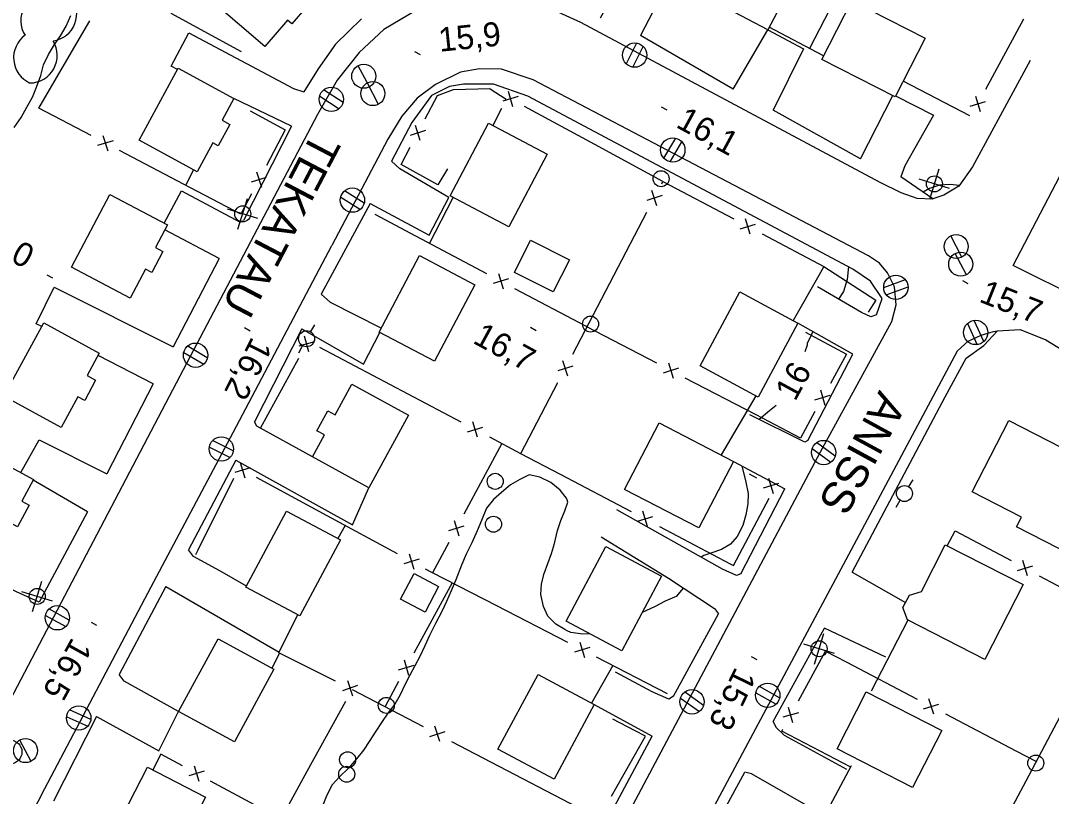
# Model space of a CAD drawing. Extents: x 219136 to 222520, y 5421589 to 5424530.
# Drawn here: x 220439.8 to 220568.6, y 5423964.5 to 5424061.3 of the extents above; entities that cross this region are included whole.
import ezdxf

# ---------------------------------------------------------------- set-up
doc = ezdxf.new("R2010")
doc.units = 0
for name, color, linetype in [('Level 19', 7, 'Continuous'), ('Level 2', 7, 'Continuous'), ('Level 21', 7, 'Continuous'), ('Level 3', 7, 'Continuous'), ('Level 31', 7, 'Continuous'), ('Level 36', 7, 'Continuous'), ('Level 37', 7, 'Continuous'), ('Level 44', 7, 'Continuous')]:
    doc.layers.add(name, color=color, linetype=linetype)

msp = doc.modelspace()

# ---------------------------------------------------------------- linework, layer by layer
at = {"layer": 'Level 19'}
for points in [[(220512.29, 5424061.68), (220516.28, 5424068.95), (220520.94, 5424066.53), (220517.29, 5424059.47)], [(220459.45, 5424055.23), (220458.64, 5424055.64), (220460.88, 5424059.78), (220473.94, 5424052.85), (220475.23, 5424052.42)], [(220528.84, 5424052.74), (220533.2, 5424060.17), (220537.65, 5424057.78), (220533.86, 5424050.12)], [(220473.67, 5424048.15), (220466.49, 5424051.61)], [(220544.75, 5424044.06), (220548.79, 5424051.95)], [(220549.15, 5424051.91), (220553.87, 5424049.5), (220550.32, 5424043.18), (220549.81, 5424041.8)], [(220483.53, 5424038.48), (220490.9, 5424034.54), (220493.33, 5424039.23), (220487.21, 5424042.8), (220486.18, 5424043.78)], [(220457.77, 5424036.03), (220459.94, 5424040.05), (220467.29, 5424036.17), (220467.68, 5424036.36)], [(220464.64, 5424031.6), (220457.88, 5424035.19)], [(220442.48, 5424023.11), (220441.81, 5424023.46), (220444.03, 5424028.03), (220458.89, 5424020.58)], [(220546.77, 5424024.57), (220546.06, 5424024.34), (220544.88, 5424024.86), (220539.38, 5424028.07)], [(220484.9, 5424022.92), (220478.57, 5424026.1), (220477.39, 5424027.16)], [(220543.79, 5424019.65), (220536.94, 5424023.56)], [(220474.97, 5424022.84), (220482.66, 5424018.43), (220484.72, 5424022.39)], [(220456.39, 5424015.96), (220449.52, 5424019.49)], [(220538.19, 5424008.9), (220537.8, 5424008.69), (220530.93, 5424012.1)], [(220476.29, 5424006.83), (220469.36, 5424010.66), (220469.06, 5424011.21)], [(220439.88, 5424004.89), (220442.15, 5424008.97), (220450.6, 5424004.71)], [(220466.72, 5424006.45), (220481.3, 5423998.36), (220483.34, 5424002.98)], [(220528.88, 5424006.28), (220535.31, 5424002.87)], [(220448.19, 5424000), (220441.41, 5424003.93)], [(220529.8, 5423992.23), (220529.28, 5423992.02), (220527.54, 5423992.82), (220514.32, 5424000.25)], [(220512.36, 5423996.85), (220520.77, 5423991.69), (220526.51, 5423987.91), (220527.03, 5423987.26)], [(220442.18, 5423988.72), (220439.33, 5423990.01), (220428.37, 5423995.69)], [(220468.06, 5423990.72), (220464.74, 5423992.63), (220461.43, 5423994.41), (220460.8, 5423995.24)], [(220543.71, 5423992.44), (220550.38, 5423988.65)], [(220458, 5423990.64), (220472.15, 5423982.47)], [(220547.91, 5423981.83), (220540.27, 5423985.44)], [(220449.34, 5423974.44), (220457.1, 5423970.16), (220459.59, 5423975.04), (220452.78, 5423978.86), (220452.15, 5423979.68)], [(220521.42, 5423976.98), (220520.81, 5423976.61), (220518.73, 5423977.5), (220514.16, 5423979.96)], [(220511.49, 5423975.93), (220518.72, 5423971.97)], [(220533.85, 5423973.82), (220534.2, 5423973.09), (220535.25, 5423972.08), (220543, 5423967.84)], [(220540.03, 5423962.18), (220531.14, 5423967.27), (220530.32, 5423967.46)]]:
    msp.add_lwpolyline(points, dxfattribs=at)
at = {"layer": 'Level 2'}
for points in [[(220439.05, 5424047.96), (220439.91, 5424049.2), (220440.64, 5424050.5), (220441.32, 5424051.74), (220441.84, 5424053.01), (220442.37, 5424054.45), (220442.69, 5424055.8), (220443.35, 5424057.09), (220444.06, 5424058.32), (220444.82, 5424059.41), (220445.53, 5424060.61), (220446.14, 5424061.94)], [(220557.1, 5424040.73), (220555.95, 5424040.85), (220554.64, 5424040.79), (220553.37, 5424040.34), (220552.6, 5424039.9)], [(220543.26, 5424030.6), (220543.08, 5424029), (220542.63, 5424027.51), (220542.03, 5424026.52)], [(220538.82, 5424022.49), (220538.46, 5424021.75), (220538.1, 5424021.05), (220538.09, 5424020.78), (220537.81, 5424019.95)], [(220534.23, 5424013.26), (220533.38, 5424012.6), (220532.12, 5424011.51)], [(220529.95, 5424005.71), (220530.46, 5424003.68), (220530.72, 5424002.26), (220530.7, 5424001), (220530.43, 5423999.6), (220530.07, 5423998.29), (220529.36, 5423996.92), (220528.52, 5423995.94), (220527.42, 5423995.3), (220526.07, 5423994.82), (220525.2, 5423994.55), (220524.87, 5423994.32)], [(220507.34, 5423998.91), (220507.84, 5424000.1), (220508.19, 5424001.17), (220508.14, 5424001.47), (220508.02, 5424001.69), (220507.23, 5424002.67), (220506.07, 5424003.63), (220504.72, 5424004.31), (220503.37, 5424004.6), (220502.23, 5424004.01), (220501.05, 5424003.35), (220499.91, 5424002.4), (220498.93, 5424001.53), (220498.05, 5424000.42), (220497.41, 5423998.91), (220496.86, 5423997.59), (220496.21, 5423996.1), (220495.49, 5423994.68), (220494.91, 5423993.33), (220494.22, 5423991.5), (220493.64, 5423990.11), (220493.04, 5423988.78), (220492.47, 5423987.55), (220491.69, 5423986.02), (220490.94, 5423984.53), (220490.34, 5423983.24), (220489.73, 5423981.91), (220489.11, 5423980.74), (220488.46, 5423979.58), (220487.85, 5423978.4), (220487.27, 5423977.15), (220486.58, 5423975.98), (220485.72, 5423974.83), (220484.92, 5423973.67), (220484.24, 5423972.6), (220483.4, 5423971.3), (220482.68, 5423970.24), (220481.82, 5423969.13), (220480.8, 5423967.97), (220479.68, 5423966.9), (220478.78, 5423965.91), (220478.09, 5423964.59), (220477.51, 5423963.16)], [(220510.96, 5423984.76), (220510.07, 5423984.7), (220508.57, 5423984.9), (220508.11, 5423985.14), (220507.84, 5423985.28), (220506.69, 5423985.95), (220505.7, 5423986.96), (220505.16, 5423988.16), (220504.83, 5423989.66), (220504.9, 5423991), (220505.26, 5423992.28), (220505.72, 5423993.55), (220506.17, 5423994.79), (220506.52, 5423996.01), (220506.92, 5423997.67), (220507.34, 5423998.91)], [(220522.62, 5423990.47), (220521.75, 5423989.42), (220521.51, 5423989.31), (220520.35, 5423988.81), (220519.03, 5423988.12), (220517.49, 5423987.42)]]:
    msp.add_lwpolyline(points, dxfattribs=at)
at = {"layer": 'Level 21'}
for points in [[(220553.81, 5424039.07), (220553.73, 5424039.04), (220551.84, 5424039.1), (220549.83, 5424039.83), (220547.23, 5424041.1), (220509.83, 5424061.1), (220505.16, 5424063.19), (220501.63, 5424064.07), (220497.84, 5424064.31), (220493.34, 5424063.78), (220489.3, 5424062.62), (220485.23, 5424060.19), (220482.14, 5424057.35), (220479.4, 5424053.9), (220476.93, 5424049.58), (220459.72, 5424016.93), (220442.62, 5423984.31), (220432.48, 5423964.99)], [(220482.45, 5424061.53), (220479.2, 5424058.39), (220477, 5424055.31), (220475.23, 5424052.42)], [(220528.84, 5424052.74), (220517.29, 5424059.47)], [(220565.98, 5424056.33), (220558.77, 5424043.06), (220557.04, 5424040.64), (220555.17, 5424039.54), (220553.81, 5424039.07)], [(220482, 5423898.19), (220509.57, 5423950.66), (220539.78, 5424007.46), (220548.68, 5424023.76), (220549.21, 5424025.83), (220549.01, 5424028.08), (220548.12, 5424029.81), (220547.12, 5424031.04), (220545.76, 5424031.95), (220503.88, 5424053.94), (220499.93, 5424055.25), (220497.16, 5424055.31), (220494.79, 5424054.89), (220491.67, 5424053.35), (220489.4, 5424051.62), (220487.45, 5424049.39), (220485.72, 5424046.5), (220478.71, 5424033.22)], [(220563.85, 5424030.74), (220575.98, 5424054)], [(220546.77, 5424024.57), (220547.46, 5424026.6), (220546.03, 5424028.77), (220543.82, 5424030.3), (220503.2, 5424051.89), (220498.94, 5424053.4), (220495.17, 5424053.37), (220493.41, 5424053.1), (220491.17, 5424051.95), (220488.71, 5424048.6), (220486.18, 5424043.78)], [(220544.75, 5424044.06), (220533.86, 5424050.12)], [(220473.67, 5424048.15), (220467.68, 5424036.36)], [(220553.81, 5424039.07), (220549.81, 5424041.8)], [(220483.53, 5424038.48), (220477.39, 5424027.16)], [(220442.46, 5423964.65), (220456.17, 5423990.6), (220466.42, 5424009.9), (220478.71, 5424033.22)], [(220464.64, 5424031.6), (220458.89, 5424020.58)], [(220676.08, 5424018.63), (220666.81, 5424018.72), (220652.54, 5424017.6), (220634.28, 5424015.11), (220619.73, 5424013.71), (220610.04, 5424013.54), (220600.68, 5424014.59), (220591.85, 5424016.88), (220585.82, 5424019.78), (220572.39, 5424026.5), (220563.85, 5424030.74)], [(220474.97, 5424022.84), (220469.06, 5424011.21)], [(220515.26, 5423942.18), (220542.96, 5423994.03), (220556.9, 5424020.07), (220558.21, 5424021.28), (220559.84, 5424022.03), (220561.38, 5424022.5), (220561.87, 5424022.58)], [(220543.71, 5423992.44), (220555.33, 5424014.35), (220557.98, 5424019.15), (220560.16, 5424020.76), (220561.87, 5424022.58)], [(220561.87, 5424022.58), (220564.7, 5424022.75), (220567.91, 5424021.46), (220575.55, 5424016.81), (220585.23, 5424011.37), (220590.42, 5424008.96), (220595.9, 5424007.27), (220603.45, 5424005.98), (220611.39, 5424005.57), (220619.3, 5424005.57), (220628.95, 5424006.59), (220644.83, 5424008.82), (220657.83, 5424010.52), (220666.08, 5424011.08), (220675.19, 5424010.61)], [(220538.19, 5424008.9), (220543.79, 5424019.65)], [(220456.39, 5424015.96), (220450.6, 5424004.71)], [(220466.72, 5424006.45), (220460.8, 5423995.24)], [(220529.8, 5423992.23), (220535.31, 5424002.87)], [(220448.19, 5424000), (220442.18, 5423988.72)], [(220458, 5423990.64), (220452.15, 5423979.68)], [(220521.42, 5423976.98), (220527.03, 5423987.26)], [(220533.85, 5423973.82), (220540.27, 5423985.44)], [(220449.34, 5423974.44), (220443.96, 5423963.84)], [(220512.82, 5423960.95), (220518.72, 5423971.97)], [(220514.33, 5423939), (220518.69, 5423946.15), (220530.32, 5423967.46)], [(220442.46, 5423964.65), (220422.6, 5423926.81), (220405.91, 5423895.13), (220405.34, 5423893.3), (220405.48, 5423891.29), (220406.31, 5423889.36), (220407.36, 5423888.04), (220408.77, 5423887.25), (220456.11, 5423861.87), (220458.55, 5423861.53), (220461.44, 5423862.16), (220463.45, 5423863.69), (220465.2, 5423866.45), (220482, 5423898.19)]]:
    msp.add_lwpolyline(points, dxfattribs=at)
at = {"layer": 'Level 3'}
for p, q in [((220489.07, 5424057.45), (220489.76, 5424057.07)), ((220519.86, 5424050.54), (220520.56, 5424050.16)), ((220443.11, 5424029.56), (220443.81, 5424029.18)), ((220557.5, 5424028.87), (220558.19, 5424028.49)), ((220467.83, 5424022.98), (220468.52, 5424022.6)), ((220503.56, 5424023.02), (220504.25, 5424022.64)), ((220448.64, 5423986.21), (220449.34, 5423985.83)), ((220531.12, 5423981.91), (220531.82, 5423981.53))]:
    msp.add_line(p, q, dxfattribs=at)
at = {"layer": 'Level 31'}
for points in [[(220533.2, 5424060.17), (220524.07, 5424064.99), (220527.92, 5424072.27), (220537.04, 5424067.45)], [(220464.03, 5424063.49), (220470.77, 5424071.38), (220476.91, 5424066.14), (220474.85, 5424063.73), (220475.6, 5424063.09), (220473.72, 5424060.9), (220473.17, 5424061.37), (220470.36, 5424058.08)], [(220549.09, 5424051.8), (220539.93, 5424056.46), (220543.67, 5424063.8), (220552.83, 5424059.13)], [(220454.64, 5424046.37), (220459.54, 5424055.39), (220466.49, 5424051.61), (220465.01, 5424048.88), (220465.98, 5424048.36), (220464.53, 5424045.68), (220463.85, 5424046.05), (220461.89, 5424042.43)], [(220505.64, 5424044.65), (220500.85, 5424035.56), (220493.5, 5424039.42), (220498.3, 5424048.52)], [(220446.21, 5424030.54), (220450.99, 5424039.6), (220458.2, 5424035.8), (220456.71, 5424032.97), (220457.61, 5424032.5), (220456.22, 5424029.87), (220455.45, 5424030.28), (220453.55, 5424026.67)], [(220501.53, 5424029.88), (220503.54, 5424033.89), (220508.4, 5424031.46), (220506.39, 5424027.45)], [(220496.6, 5424028.34), (220491.57, 5424018.78), (220484.64, 5424022.43), (220489.67, 5424031.98)], [(220536.94, 5424023.56), (220531.99, 5424014.31), (220524.73, 5424018.2), (220529.68, 5424027.45)], [(220437.75, 5424014.44), (220442.73, 5424023.57), (220449.68, 5424019.78), (220448.16, 5424017), (220449.22, 5424016.42), (220447.85, 5424013.9), (220447.01, 5424014.36), (220444.92, 5424010.53)], [(220488.3, 5424012.05), (220483.34, 5424002.98), (220476.29, 5424006.83), (220477.81, 5424009.6), (220476.87, 5424010.11), (220478.22, 5424012.58), (220479.13, 5424012.09), (220481.22, 5424015.91)], [(220563.3, 5424011.4), (220576.46, 5424004.64), (220571.25, 5423994.51), (220564.25, 5423998.11), (220564.88, 5423999.33), (220558.72, 5424002.49)], [(220515.3, 5424002.77), (220519.6, 5424011.08), (220528.88, 5424006.28), (220524.59, 5423997.97)], [(220429.29, 5423998.76), (220434.22, 5424007.93), (220441.47, 5424004.03), (220440, 5424001.31), (220440.92, 5424000.81), (220439.46, 5423998.1), (220438.61, 5423998.55), (220436.6, 5423994.83)], [(220479.8, 5423996.47), (220474.73, 5423986.99), (220467.99, 5423990.59), (220473.06, 5424000.07)], [(220555.35, 5423995.87), (220565.1, 5423990.89), (220560.31, 5423981.53), (220550.65, 5423986.48), (220550.05, 5423988.03), (220550.89, 5423989.59), (220552.38, 5423990.04)], [(220508.01, 5423986.33), (220512.97, 5423995.66), (220519.91, 5423991.97), (220514.95, 5423982.64)], [(220490.38, 5423987.47), (220487.3, 5423989.09), (220488.99, 5423992.3), (220492.07, 5423990.67)], [(220471.5, 5423980.34), (220466.58, 5423971.25), (220459.59, 5423975.04), (220464.51, 5423984.12)], [(220499.48, 5423970.36), (220504.48, 5423979.69), (220511.49, 5423975.93), (220506.48, 5423966.6)], [(220545.48, 5423977.49), (220554.91, 5423972.66), (220551.28, 5423965.58), (220541.85, 5423970.41)], [(220462.96, 5423964.37), (220458.28, 5423955.3), (220451.02, 5423959.04), (220455.69, 5423968.12)]]:
    msp.add_lwpolyline(points, close=True, dxfattribs=at)
at = {"layer": 'Level 36'}
for p, q in [((220516.8, 5424058.5), (220515.49, 5424055.92)), ((220516.32, 5424055.52), (220517.63, 5424058.1)), ((220483.42, 5424053.03), (220482.02, 5424055.69)), ((220480.13, 5424051.11), (220477.69, 5424052.68)), ((220484.56, 5424050.86), (220483.16, 5424053.52)), ((220477.21, 5424051.89), (220479.65, 5424050.32)), ((220521.65, 5424046.64), (220520.17, 5424044.15)), ((220520.97, 5424043.7), (220522.45, 5424046.19)), ((220553.41, 5424039.02), (220554.58, 5424042.83)), ((220555.9, 5424040.34), (220552.09, 5424041.51)), ((220482.77, 5424038.52), (220480.3, 5424040.05)), ((220467, 5424035.28), (220468.17, 5424039.09)), ((220479.83, 5424039.26), (220482.3, 5424037.73)), ((220469.49, 5424036.6), (220465.68, 5424037.77)), ((220557.43, 5424031.77), (220556.03, 5424034.43)), ((220557.99, 5424029.57), (220556.59, 5424032.23)), ((220550.36, 5424028.94), (220547.64, 5424027.94)), ((220547.98, 5424027.08), (220550.7, 5424028.08)), ((220476.55, 5424023.35), (220476.06, 5424022.48)), ((220558.14, 5424023.5), (220559.32, 5424020.85)), ((220560.16, 5424021.24), (220558.98, 5424023.89)), ((220463.17, 5424019.22), (220460.67, 5424020.69)), ((220474.61, 5424019.85), (220475.08, 5424020.73)), ((220460.23, 5424019.88), (220462.73, 5424018.41)), ((220466.41, 5424007.58), (220463.82, 5424008.89)), ((220463.43, 5424008.06), (220466.02, 5424006.75)), ((220538.72, 5424007.87), (220541.07, 5424006.17)), ((220541.6, 5424006.93), (220539.25, 5424008.63)), ((220551.29, 5424003.99), (220550.78, 5424003.13)), ((220549.24, 5424000.55), (220549.74, 5424001.42)), ((220441.33, 5423987.52), (220442.5, 5423991.33)), ((220443.82, 5423988.84), (220440.01, 5423990.01)), ((220442.95, 5423987.05), (220445.49, 5423985.65)), ((220445.91, 5423986.47), (220443.37, 5423987.87)), ((220539.01, 5423980.98), (220540.18, 5423984.79)), ((220541.5, 5423982.3), (220537.69, 5423983.47)), ((220534.66, 5423976.76), (220532.14, 5423978.19)), ((220522.27, 5423976.72), (220524.64, 5423975.05)), ((220525.15, 5423975.82), (220522.78, 5423977.49)), ((220531.7, 5423977.38), (220534.22, 5423975.95)), ((220448.61, 5423974.07), (220445.96, 5423975.24)), ((220445.61, 5423974.39), (220448.26, 5423973.22)), ((220441.17, 5423968.83), (220439.77, 5423971.49))]:
    msp.add_line(p, q, dxfattribs=at)
for centre, radius in [((220516.55, 5424057.01), 1.52), ((220482.71, 5424054.37), 1.5), ((220478.67, 5424051.49), 1.52), ((220483.85, 5424052.2), 1.5), ((220521.32, 5424045.17), 1.52), ((220519.85, 5424041.58), 1), ((220554, 5424040.93), 1), ((220481.3, 5424038.9), 1.52), ((220467.59, 5424037.19), 1), ((220556.72, 5424033.11), 1.5), ((220557.28, 5424030.91), 1.5), ((220549.18, 5424028.01), 1.52), ((220511.04, 5424023.43), 1), ((220559.15, 5424022.38), 1.52), ((220475.57, 5424021.6), 1), ((220461.7, 5424019.54), 1.52), ((220464.92, 5424007.83), 1.52), ((220540.16, 5424007.39), 1.52), ((220499.13, 5424003.79), 1), ((220550.26, 5424002.27), 1), ((220498.92, 5423998.44), 1), ((220441.92, 5423989.43), 1), ((220444.43, 5423986.75), 1.52), ((220539.6, 5423982.89), 1), ((220523.71, 5423976.26), 1.52), ((220533.18, 5423977.08), 1.52), ((220485.53, 5423975.82), 1), ((220447.11, 5423974.24), 1.52), ((220438.51, 5423970), 1.5), ((220440.46, 5423970.17), 1.5), ((220480.7, 5423969.03), 1), ((220566.66, 5423968.61), 1), ((220480.58, 5423967.22), 1)]:
    msp.add_circle(centre, radius, dxfattribs=at)
at = {"layer": 'Level 37'}
for p, q in [((220500.74, 5424052.5), (220501.31, 5424050.58)), ((220501.99, 5424051.83), (220500.07, 5424051.25)), ((220558.48, 5424050.65), (220560.4, 5424051.22)), ((220559.15, 5424051.89), (220559.73, 5424049.98)), ((220490.41, 5424047.59), (220488.5, 5424046.99)), ((220489.75, 5424046.33), (220489.16, 5424048.24)), ((220451.39, 5424046.32), (220449.47, 5424045.73)), ((220450.13, 5424046.98), (220450.73, 5424045.07)), ((220469.33, 5424042.43), (220469.92, 5424040.52)), ((220468.67, 5424041.18), (220470.58, 5424041.77)), ((220519.31, 5424038.21), (220518.71, 5424040.12)), ((220519.97, 5424039.46), (220518.06, 5424038.86)), ((220529.75, 5424035.33), (220531.66, 5424035.92)), ((220531, 5424034.67), (220530.41, 5424036.58)), ((220499.54, 5424029.74), (220500.13, 5424027.82)), ((220500.79, 5424029.07), (220498.88, 5424028.49)), ((220475.86, 5424019.97), (220475.29, 5424021.9)), ((220476.54, 5424021.22), (220474.61, 5424020.65)), ((220508.85, 5424018.19), (220506.94, 5424017.59)), ((220508.19, 5424016.94), (220507.59, 5424018.85)), ((220522.03, 5424017.92), (220520.12, 5424017.31)), ((220520.78, 5424018.57), (220521.38, 5424016.66)), ((220539.75, 5424015.22), (220540.31, 5424013.29)), ((220539.07, 5424013.98), (220540.99, 5424014.53)), ((220495.68, 5424009.97), (220497.59, 5424010.56)), ((220496.93, 5424009.31), (220496.34, 5424011.23)), ((220467.29, 5424006.16), (220467.86, 5424004.24)), ((220468.53, 5424005.48), (220466.62, 5424004.91)), ((220534.52, 5424003.54), (220532.61, 5424002.95)), ((220533.27, 5424004.2), (220533.86, 5424002.29)), ((220518.17, 5423998.14), (220517.57, 5424000.05)), ((220494, 5423998.89), (220494.58, 5423996.98)), ((220516.92, 5423998.8), (220518.83, 5423999.39)), ((220493.33, 5423997.65), (220495.25, 5423998.23)), ((220488.4, 5423994.74), (220488.97, 5423992.82)), ((220489.64, 5423994.06), (220487.72, 5423993.49)), ((220564.38, 5423992.66), (220566.29, 5423993.24)), ((220565.63, 5423991.99), (220565.04, 5423993.91)), ((220510.95, 5423983.05), (220509.04, 5423982.44)), ((220509.69, 5423983.7), (220510.3, 5423981.79)), ((220487.07, 5423980.27), (220488.99, 5423980.84)), ((220487.74, 5423981.52), (220488.31, 5423979.6)), ((220481.94, 5423978.28), (220480.04, 5423977.65)), ((220480.67, 5423978.91), (220481.31, 5423977.02)), ((220553.91, 5423974.73), (220553.31, 5423976.64)), ((220536.32, 5423973.65), (220535.76, 5423975.57)), ((220552.65, 5423975.38), (220554.56, 5423975.98)), ((220537, 5423974.9), (220535.08, 5423974.33)), ((220492.21, 5423971.3), (220491.61, 5423973.21)), ((220490.95, 5423971.95), (220492.87, 5423972.55)), ((220462.78, 5423967.6), (220460.86, 5423967.03)), ((220461.53, 5423968.27), (220462.11, 5423966.36))]:
    msp.add_line(p, q, dxfattribs=at)
for points in [[(220542.17, 5424065.21), (220538.38, 5424057.84)], [(220458.63, 5424062.24), (220467.41, 5424057.45)], [(220565.11, 5424061.51), (220560.38, 5424052.7)], [(220443.45, 5424052.66), (220448.48, 5424061.3)], [(220540.16, 5424056.9), (220533.37, 5424060.49)], [(220558.41, 5424049.44), (220550.09, 5424053.76)], [(220448.66, 5424046.96), (220442.13, 5424050.39), (220443.45, 5424052.66)], [(220490.38, 5424049.06), (220491.91, 5424051.97), (220493.91, 5424052.7), (220498.47, 5424052.82), (220498.49, 5424052.81)], [(220498.49, 5424052.81), (220500.51, 5424051.5)], [(220468.53, 5424050.06), (220472.9, 5424047.69), (220470.56, 5424043.24)], [(220499.93, 5424050.36), (220498.85, 5424048.23)], [(220511.58, 5424045.83), (220502.79, 5424050.59)], [(220461.05, 5424040.44), (220452.2, 5424045.1)], [(220493.16, 5424042.8), (220491.96, 5424040.81), (220487.39, 5424043.35), (220488.53, 5424045.52)], [(220519.94, 5424040.93), (220520.09, 5424041.22), (220511.58, 5424045.83)], [(220460.49, 5424040.74), (220461.45, 5424042.67)], [(220520.09, 5424041.22), (220528.94, 5424036.56)], [(220468.69, 5424039.7), (220467.34, 5424037.14), (220461.05, 5424040.44)], [(220490.93, 5424033.5), (220493.89, 5424039.21)], [(220489.23, 5424034.4), (220484.15, 5424037.1)], [(220513.45, 5424028.53), (220518.09, 5424037.39)], [(220532.47, 5424034.69), (220540.19, 5424030.62), (220539.56, 5424029.51)], [(220498.07, 5424029.72), (220489.23, 5424034.4)], [(220540.19, 5424030.62), (220546.69, 5424026.42), (220545.71, 5424024.9)], [(220539.56, 5424029.51), (220536.36, 5424023.87)], [(220508.82, 5424019.67), (220513.45, 5424028.53)], [(220510.44, 5424023.16), (220501.6, 5424027.84)], [(220519.31, 5424018.54), (220510.6, 5424023.07), (220510.44, 5424023.16)], [(220537.9, 5424022.42), (220543.02, 5424019.68), (220541, 5424016.01)], [(220477.18, 5424020.55), (220486.02, 5424015.87)], [(220469.81, 5424010.41), (220474.61, 5424019.18)], [(220531.72, 5424012.08), (220522.85, 5424016.69)], [(220486.02, 5424015.87), (220494.86, 5424011.2)], [(220502.33, 5424007.26), (220506.96, 5424016.12)], [(220531.7, 5424014.47), (220527.34, 5424007.08)], [(220539.07, 5424012.5), (220537.25, 5424009.2), (220531.72, 5424012.08)], [(220498.4, 5424009.34), (220502.31, 5424007.27), (220507.25, 5424004.68)], [(220499.96, 5424008.51), (220495.23, 5423999.7)], [(220466.45, 5424004.13), (220461.98, 5423995.19)], [(220478.13, 5423999.49), (220469.33, 5424004.25)], [(220507.25, 5424004.68), (220516.1, 5424000.02)], [(220531.8, 5424004.18), (220530.88, 5424004.67)], [(220528.5, 5423993.51), (220528.92, 5423993.29), (220533.37, 5424001.71)], [(220486.92, 5423994.73), (220478.13, 5423999.49)], [(220480.37, 5423998.28), (220479.47, 5423996.65)], [(220519.64, 5423998.16), (220528.5, 5423993.51)], [(220555.61, 5423995.74), (220556.61, 5423997.6), (220563.57, 5423993.89)], [(220493.34, 5423996.17), (220491.3, 5423992.37), (220491.3, 5423992.36)], [(220461.98, 5423995.19), (220461.68, 5423994.6)], [(220499.33, 5423988.23), (220491.3, 5423992.36), (220490.44, 5423992.82)], [(220567.1, 5423992.01), (220575.93, 5423987.31)], [(220493.74, 5423991.11), (220488.98, 5423982.32)], [(220508.22, 5423983.66), (220499.33, 5423988.23)], [(220473.03, 5423984.23), (220474.49, 5423987.12)], [(220550.68, 5423986.47), (220546.08, 5423977.59)], [(220479.2, 5423978.85), (220472.1, 5423982.38), (220473.03, 5423984.23)], [(220472.18, 5423982.34), (220471.24, 5423980.48)], [(220520.67, 5423977.26), (220511.78, 5423981.83)], [(220537, 5423976.37), (220540.39, 5423982.59), (220542.97, 5423981.24)], [(220513.82, 5423980.78), (220511.15, 5423976.11)], [(220542.97, 5423981.24), (220551.84, 5423976.61)], [(220481.28, 5423977.82), (220490.14, 5423973.18)], [(220487.07, 5423978.8), (220485.38, 5423975.67)], [(220475.66, 5423967.59), (220480.47, 5423976.35)], [(220516.63, 5423972.62), (220513.82, 5423974.08)], [(220555.38, 5423974.76), (220564.24, 5423970.12)], [(220570.1, 5423975.17), (220565.4, 5423966.34)], [(220543.54, 5423968.1), (220534.94, 5423972.6), (220535.08, 5423972.86)], [(220513.67, 5423964.5), (220517.9, 5423971.96), (220516.63, 5423972.62)], [(220493.68, 5423971.32), (220502.54, 5423966.69)], [(220564.24, 5423970.12), (220566.68, 5423968.85), (220566.72, 5423968.83)], [(220460.06, 5423968.26), (220457.35, 5423969.72), (220456.38, 5423967.76)], [(220470.85, 5423958.82), (220475.66, 5423967.59)], [(220538.93, 5423959.52), (220538.96, 5423959.58), (220543.66, 5423968.33)], [(220472.39, 5423961.63), (220463.58, 5423966.37)], [(220502.54, 5423966.69), (220511.4, 5423962.05)], [(220565.4, 5423966.34), (220560.71, 5423957.51)]]:
    msp.add_lwpolyline(points, dxfattribs=at)
at = {"layer": 'Level 44'}
for centre, start, end in [((220443.32, 5424061.35), 92.4856, 212.4856), ((220443.4, 5424062.19), 278.8712, 38.8712), ((220442.43, 5424056.68), 125.9158, 245.9158), ((220440.96, 5424056.99), 270.8801, 30.8801)]:
    msp.add_arc(centre, 3.46, start, end, dxfattribs=at)

# ---------------------------------------------------------------- texts
at = {"layer": 'Level 2'}
msp.add_text('16', height=3, rotation=61.4505, dxfattribs=at).set_placement((220536.6, 5424013.68))
at = {"layer": 'Level 21'}
for s, rotation, p in [('TEKATAU', 242.3357, (220476.37, 5424047.6)), ('ANISS', 241.3649, (220547.14, 5424015.27))]:
    msp.add_text(s, height=4, rotation=rotation, dxfattribs=at).set_placement(p)
at = {"layer": 'Level 3'}
for s, rotation, p in [('15,9', 5.9056, (220492.2, 5424057.42)), ('16,1', 331.383, (220521.58, 5424048.08)), ('17,0', 331.383, (220433.56, 5424034.01)), ('15,7', 338.3389, (220559.45, 5424026.26)), ('16,7', 331.383, (220496.2, 5424021.13)), ('16,2', 243.0156, (220468.75, 5424021.95)), ('16,5', 241.102, (220446.29, 5423984.42)), ('15,3', 244.1573, (220529.15, 5423980.72))]:
    msp.add_text(s, height=3, rotation=rotation, dxfattribs=at).set_placement(p)

doc.saveas('drawing.dxf')
